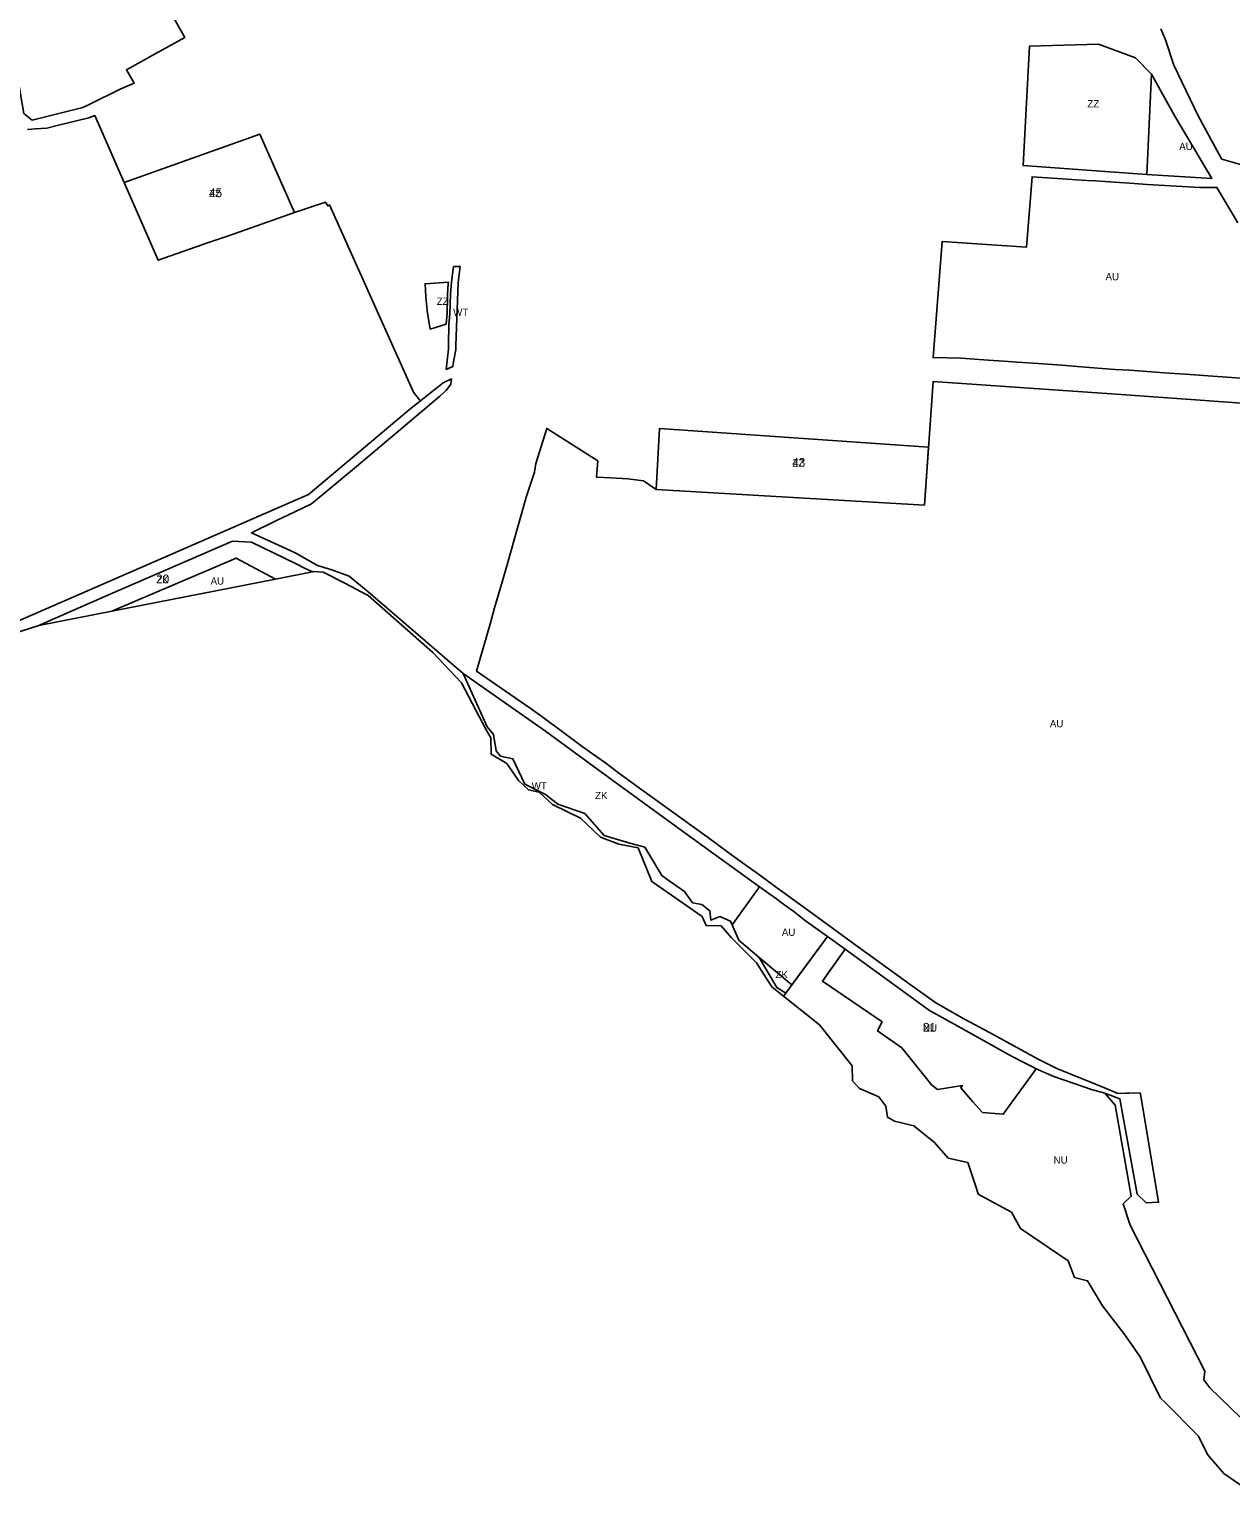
# Model space of a CAD drawing. Extents: x -541351 to -537540, y -1162694 to -1159725.
# Drawn here: x -540284 to -539459, y -1162132 to -1161126 of the extents above; entities that cross this region are included whole.
import ezdxf

# ---------------------------------------------------------------- set-up
doc = ezdxf.new("R2010")
doc.units = 0
for name, color, linetype in [('90640013', 7, 'Continuous'), ('90670013', 7, 'Continuous'), ('90670023', 7, 'Continuous'), ('90710013', 7, 'Continuous'), ('90710023', 7, 'Continuous'), ('90730013', 7, 'Continuous'), ('90730023', 7, 'Continuous'), ('90750013', 7, 'Continuous'), ('90910012', 7, 'Continuous'), ('ID_navrh', 7, 'Continuous')]:
    doc.layers.add(name, color=color, linetype=linetype)

msp = doc.modelspace()

# ---------------------------------------------------------------- linework, layer by layer
at = {"layer": '90640013'}
msp.add_lwpolyline([(-539992.48, -1161289.13), (-539987.89, -1161289.13), (-539989.14, -1161300.05), (-539990.78, -1161343.53), (-539990.84, -1161345.21), (-539990.88, -1161346.21), (-539992.72, -1161355.93), (-539992.93, -1161357.91), (-539992.93, -1161357.91), (-539997.43, -1161359.85), (-539997.43, -1161359.85), (-539995.85, -1161345.83), (-539995.82, -1161344), (-539995.8, -1161342.48), (-539995.6, -1161328.93), (-539994.93, -1161321.76), (-539994.48, -1161308.21), (-539993.82, -1161299.61)], close=True, dxfattribs=at)
msp.add_lwpolyline([(-540291.41, -1161532.59), (-540229.38, -1161505.57), (-540117.05, -1161456.65), (-540092, -1161445.78), (-540061.82, -1161420.37), (-540029.75, -1161393.37), (-540022.53, -1161387.29), (-539999.44, -1161369.08), (-539993.83, -1161366.31), (-539994.23, -1161370.06), (-539997.48, -1161374.21), (-540001.8, -1161378.25), (-540027.01, -1161399.42), (-540059.11, -1161426.38), (-540089.93, -1161452.04), (-540101.4, -1161457.57), (-540113.86, -1161463.58), (-540131.11, -1161472.1), (-540104.63, -1161484.12), (-540100.72, -1161485.89), (-540085.79, -1161494.36), (-540075.88, -1161497.34), (-540064.03, -1161501.76), (-540050.98, -1161512.57), (-539985.72, -1161568.53), (-539969.3, -1161605.18), (-539964.88, -1161610.52), (-539963.08, -1161621.82), (-539960.17, -1161625.29), (-539951.61, -1161627.12), (-539943.52, -1161644.57), (-539929.21, -1161651.77), (-539920.76, -1161658.22), (-539902.3, -1161664.83), (-539889.07, -1161679.88), (-539871.42, -1161685.18), (-539861.03, -1161687.93), (-539849.43, -1161707.39), (-539844.32, -1161711.05), (-539833.88, -1161718.35), (-539828.42, -1161726.07), (-539822.05, -1161727.27), (-539816.41, -1161731.54), (-539815.88, -1161737.88), (-539809.68, -1161735.52), (-539802.4, -1161738.55), (-539801.21, -1161741.26), (-539797.55, -1161749.61), (-539796.59, -1161751.79), (-539794.73, -1161753.35), (-539791.85, -1161755.78), (-539782.64, -1161763.55), (-539770.56, -1161784.1), (-539764.42, -1161788.07), (-539765.97, -1161790.189), (-539774.01, -1161783.8), (-539784.55, -1161767.2), (-539801.67, -1161750.2), (-539808.77, -1161741.8), (-539819.07, -1161741.58), (-539821.75, -1161735.54), (-539856.24, -1161711.42), (-539865.78, -1161688.26), (-539878.85, -1161685.75), (-539891.59, -1161680.9), (-539905.36, -1161667.95), (-539924.53, -1161658.61), (-539933.62, -1161650.11), (-539940.98, -1161648.48), (-539947.86, -1161642.02), (-539955.83, -1161630.36), (-539966.57, -1161624.08), (-539966.81, -1161612.76), (-539969.9, -1161607.26), (-539986.85, -1161575.11), (-540006.67, -1161554.17), (-540050.94, -1161515.14), (-540051.8, -1161514.68), (-540067.03, -1161506.49), (-540081.86, -1161499.15), (-540088.29, -1161498.6), (-540089.29, -1161498.8), (-540092.72, -1161497.13), (-540094.64, -1161496.2), (-540100.44, -1161493.38), (-540131.11, -1161478.47), (-540144.17, -1161477.68), (-540225.98, -1161513.32), (-540265.09, -1161530.36), (-540277.11, -1161535.69), (-540306.48, -1161545.1)], dxfattribs=at)
at = {"layer": '90670013'}
for points in [[(-539513.32, -1161157.12), (-539516.59, -1161225.93), (-539557.69, -1161223.11), (-539601.36, -1161219.9), (-539597.06, -1161137.85), (-539549.61, -1161136.48), (-539524.21, -1161145.9)], [(-539995.94, -1161299.88), (-539996.01, -1161301.19), (-539996.61, -1161308.12), (-539996.7, -1161321.56), (-539997.52, -1161328.72), (-540008.53, -1161332.12), (-540010.29, -1161321.38), (-540011.49, -1161309.94), (-540011.93, -1161301.03)]]:
    msp.add_lwpolyline(points, close=True, dxfattribs=at)
at = {"layer": '90670023'}
for points in [[(-540101.51, -1161252.18), (-540146.906, -1161268.009), (-540160.494, -1161272.74), (-540195.185, -1161284.798), (-540218.502, -1161231.526), (-540125.366, -1161198.286)], [(-539669.156, -1161452.992), (-539853.39, -1161442.31), (-539850.918, -1161400.307), (-539666.343, -1161413.186)]]:
    msp.add_lwpolyline(points, close=True, dxfattribs=at)
at = {"layer": '90710013'}
for points in [[(-539929.16, -1161608.15), (-539882.99, -1161642.02), (-539832.65, -1161678.79), (-539782.3, -1161715.02), (-539801.21, -1161741.26), (-539802.4, -1161738.55), (-539809.68, -1161735.52), (-539815.88, -1161737.88), (-539816.41, -1161731.54), (-539822.05, -1161727.27), (-539828.42, -1161726.07), (-539833.88, -1161718.35), (-539844.32, -1161711.05), (-539849.43, -1161707.39), (-539861.03, -1161687.93), (-539871.42, -1161685.18), (-539889.07, -1161679.88), (-539902.3, -1161664.83), (-539920.76, -1161658.22), (-539929.21, -1161651.77), (-539943.52, -1161644.57), (-539951.61, -1161627.12), (-539960.17, -1161625.29), (-539963.08, -1161621.82), (-539964.88, -1161610.52), (-539969.3, -1161605.18), (-539985.72, -1161568.53)], [(-539770.56, -1161784.1), (-539782.64, -1161763.55), (-539760.252, -1161782.438), (-539764.42, -1161788.07)]]:
    msp.add_lwpolyline(points, close=True, dxfattribs=at)
at = {"layer": '90710023'}
msp.add_lwpolyline([(-540094.64, -1161496.2), (-540094.64, -1161496.2), (-540092.72, -1161497.13), (-540089.29, -1161498.8), (-540089.29, -1161498.8), (-540114.639, -1161503.779), (-540141.7, -1161489.349), (-540226.878, -1161525.824), (-540277.11, -1161535.69), (-540265.09, -1161530.36), (-540225.98, -1161513.32), (-540144.17, -1161477.68), (-540131.11, -1161478.47), (-540100.44, -1161493.38)], close=True, dxfattribs=at)
at = {"layer": '90730013'}
msp.add_lwpolyline([(-539442.45, -1162132.43), (-539463.62, -1162117.77), (-539474.98, -1162104.91), (-539480.99, -1162092.24), (-539504.16, -1162068.99), (-539507.05, -1162066.09), (-539521.19, -1162037.78), (-539531.71, -1162022.73), (-539546.89, -1162002.65), (-539557.2, -1161985.49), (-539566.21, -1161983.21), (-539570.54, -1161971.78), (-539601.83, -1161950.6), (-539603.32, -1161949.59), (-539609.42, -1161938.46), (-539621.4, -1161931.95), (-539632.22, -1161926.07), (-539633.45, -1161922.3), (-539634.39, -1161919.41), (-539639.29, -1161904.36), (-539652.86, -1161901.34), (-539662.37, -1161890.73), (-539676.56, -1161879.19), (-539689.84, -1161876.05), (-539694.57, -1161873.26), (-539695.63, -1161865.58), (-539700.55, -1161859.23), (-539713.75, -1161853.49), (-539718.56, -1161848.39), (-539718.7, -1161838.04), (-539741.15, -1161809.91), (-539765.97, -1161790.189), (-539764.42, -1161788.07), (-539735.61, -1161749.14), (-539723.58, -1161757.8), (-539735.43, -1161774.65), (-539739.22, -1161779.81), (-539698.21, -1161807.88), (-539701.39, -1161814.06), (-539684.59, -1161825.63), (-539668.79, -1161845.45), (-539664.32, -1161850.94), (-539660.14, -1161854.23), (-539643.11, -1161851.4), (-539644.29, -1161853), (-539635.86, -1161862.6), (-539629.4, -1161869.96), (-539615.14, -1161871.21), (-539592.43, -1161840.03), (-539580.36, -1161845.31), (-539554.51, -1161854.21), (-539545.25, -1161856.85), (-539538.16, -1161865.08), (-539531.79, -1161901.38), (-539527.33, -1161927.46), (-539532.84, -1161932.62), (-539527.87, -1161947.38), (-539476.71, -1162047.7), (-539477.49, -1162053.65), (-539473.3, -1162058.96), (-539437.95, -1162093.1)], dxfattribs=at)
at = {"layer": '90730023'}
msp.add_lwpolyline([(-539603.34, -1161834.57), (-539594.06, -1161839.24), (-539592.43, -1161840.03), (-539615.14, -1161871.21), (-539629.4, -1161869.96), (-539635.86, -1161862.6), (-539644.29, -1161853), (-539643.11, -1161851.4), (-539660.14, -1161854.23), (-539664.32, -1161850.94), (-539668.79, -1161845.45), (-539684.59, -1161825.63), (-539701.39, -1161814.06), (-539698.21, -1161807.88), (-539739.22, -1161779.81), (-539735.43, -1161774.65), (-539723.58, -1161757.8), (-539665.66, -1161800.04), (-539644.29, -1161811.93), (-539622.87, -1161823.86), (-539611.45, -1161830.1)], close=True, dxfattribs=at)
at = {"layer": '90750013'}
for points in [[(-540185.73, -1161116.2), (-540176.86, -1161131.88), (-540197.26, -1161143.19), (-540216.93, -1161154.09), (-540211.6, -1161163.37), (-540221.12, -1161167.34), (-540242.426, -1161177.868), (-540246.8, -1161180.03), (-540281.58, -1161188.7), (-540287.3, -1161184.12), (-540288.43, -1161177.55), (-540294.74, -1161140.88), (-540298.48, -1161103.29)], [(-539452.22, -1161219.18), (-539464.98, -1161215.56), (-539466.8, -1161212.37), (-539481.41, -1161185.77), (-539498.11, -1161150.86), (-539503.79, -1161133.46), (-539506.91, -1161125.99)], [(-540284.83, -1161195.14), (-540279.25, -1161194.73), (-540271.57, -1161194.17), (-540264.39, -1161192.38), (-540242.79, -1161187.03), (-540238.6, -1161185.61), (-540218.502, -1161231.526), (-540195.185, -1161284.798), (-540160.494, -1161272.74), (-540146.906, -1161268.009), (-540101.51, -1161252.18), (-540080.23, -1161245.02), (-540078.75, -1161247.62), (-540077.53, -1161246.89), (-540019.81, -1161375.49), (-540015.659, -1161380.753), (-540015.115, -1161381.443), (-540022.53, -1161387.29), (-540029.75, -1161393.37), (-540061.82, -1161420.37), (-540092, -1161445.78), (-540117.05, -1161456.65), (-540229.38, -1161505.57), (-540291.41, -1161532.59)], [(-539442.69, -1161366.45), (-539490.23, -1161363.16), (-539504.725, -1161362.116), (-539528.28, -1161360.42), (-539538.26, -1161359.87), (-539547.15, -1161359.17), (-539561.62, -1161358.04), (-539574.79, -1161357.02), (-539591.1, -1161355.75), (-539605.28, -1161354.9), (-539614.66, -1161354.26), (-539625.23, -1161353.54), (-539644.31, -1161352.21), (-539663.28, -1161351.67), (-539657.046, -1161272.103), (-539599.126, -1161275.987), (-539595.35, -1161227.56), (-539581.18, -1161228.48), (-539564.86, -1161229.58), (-539557.83, -1161230.05), (-539551.82, -1161230.45), (-539535.3, -1161231.55), (-539528.25, -1161232.02), (-539516.42, -1161232.77), (-539480.24, -1161235.04), (-539468.39, -1161234.85), (-539453.999, -1161259.118)], [(-539437.95, -1162093.1), (-539473.3, -1162058.96), (-539477.49, -1162053.65), (-539476.71, -1162047.7), (-539527.87, -1161947.38), (-539532.84, -1161932.62), (-539532.84, -1161932.62), (-539527.33, -1161927.46), (-539531.79, -1161901.38), (-539538.16, -1161865.08), (-539545.25, -1161856.85), (-539535.16, -1161860.62), (-539523.09, -1161926.07), (-539517.03, -1161931.97), (-539508.43, -1161931.66), (-539520.5, -1161859.91), (-539521.049, -1161856.579), (-539528.75, -1161856.77), (-539530.99, -1161856.83), (-539536.48, -1161856.9), (-539536.48, -1161856.9), (-539545.54, -1161853.03), (-539556.8, -1161848.47), (-539562.42, -1161846.2), (-539578.2, -1161839.8), (-539591.16, -1161833.38), (-539621.96, -1161816.51), (-539634.29, -1161809.82), (-539641.65, -1161805.83), (-539661.42, -1161794.73), (-539678.99, -1161782.08), (-539719.52, -1161752.83), (-539747.55, -1161732.32), (-539770.78, -1161715.47), (-539783.08, -1161706.4), (-539792.51, -1161699.77), (-539803.22, -1161692.04), (-539811.18, -1161685.91), (-539818.4, -1161680.77), (-539828.73, -1161673.29), (-539867.18, -1161645.5), (-539879.18, -1161636.73), (-539888.88, -1161629.56), (-539896.23, -1161624.24), (-539904.11, -1161618.82), (-539923.06, -1161604.56), (-539925.41, -1161603.03), (-539931.76, -1161598.16), (-539939.69, -1161592.41), (-539976.59, -1161567.1), (-539967.01, -1161533.79), (-539964.28, -1161523.63), (-539961.04, -1161512.78), (-539957.73, -1161500.99), (-539955, -1161491.4), (-539948.74, -1161469.44), (-539942.28, -1161446.78), (-539936.89, -1161430.47), (-539935.81, -1161424.54), (-539928.46, -1161400.38), (-539893.29, -1161422.66), (-539894.17, -1161433.83), (-539884.33, -1161434.31), (-539872.87, -1161434.88), (-539861.95, -1161436.3), (-539853.39, -1161442.31), (-539669.156, -1161452.992), (-539663.153, -1161368.023), (-539603.775, -1161372.215), (-539534.132, -1161377.143), (-539505.512, -1161379.19), (-539381.181, -1161387.997)]]:
    msp.add_lwpolyline(points, dxfattribs=at)
for points in [[(-539516.59, -1161225.93), (-539513.32, -1161157.12), (-539497.36, -1161186), (-539472.01, -1161228.75)], [(-540114.639, -1161503.779), (-540114.639, -1161503.779), (-540226.878, -1161525.824), (-540141.7, -1161489.349)], [(-539735.61, -1161749.14), (-539760.252, -1161782.438), (-539782.64, -1161763.55), (-539791.85, -1161755.78), (-539794.73, -1161753.35), (-539796.59, -1161751.79), (-539797.55, -1161749.61), (-539801.21, -1161741.26), (-539782.3, -1161715.02), (-539775.92, -1161719.61), (-539772.29, -1161722.22), (-539770.71, -1161723.36), (-539769.25, -1161724.43), (-539762.51, -1161729.49), (-539758.86, -1161732.11), (-539755.49, -1161734.76), (-539751.72, -1161737.63)]]:
    msp.add_lwpolyline(points, close=True, dxfattribs=at)
at = {"layer": '90910012'}
msp.add_lwpolyline([(-539723.58, -1161757.8), (-539739.22, -1161779.81), (-539698.21, -1161807.88), (-539701.39, -1161814.06), (-539684.59, -1161825.63), (-539668.79, -1161845.45), (-539664.32, -1161850.94), (-539660.14, -1161854.23), (-539643.11, -1161851.4), (-539644.29, -1161853), (-539635.86, -1161862.6), (-539629.4, -1161869.96), (-539615.14, -1161871.21), (-539592.43, -1161840.03)], dxfattribs=at)

# ---------------------------------------------------------------- texts
at = {"layer": '90640013'}
for rotation, p in [(0, (-539992.66, -1161323.075)), (360, (-539938.746, -1161648.23))]:
    msp.add_text('WT', height=5, rotation=rotation, dxfattribs=at).set_placement(p)
at = {"layer": '90670013'}
for rotation, p in [(0, (-539557.34, -1161179.919)), (360, (-540003.935, -1161315.578))]:
    msp.add_text('ZZ', height=5, rotation=rotation, dxfattribs=at).set_placement(p)
at = {"layer": '90670023'}
for rotation, p in [(0, (-540160.168, -1161241.542)), (360, (-539759.881, -1161426.649))]:
    msp.add_text('ZZ', height=5, rotation=rotation, dxfattribs=at).set_placement(p)
at = {"layer": '90710013'}
for p in [(-539895.24, -1161654.895), (-539771.446, -1161777.793)]:
    msp.add_text('ZK', height=5, rotation=360, dxfattribs=at).set_placement(p)
at = {"layer": '90710023'}
msp.add_text('ZK', height=5, rotation=0, dxfattribs=at).set_placement((-540196.467, -1161506.685))
at = {"layer": '90730013'}
msp.add_text('NU', height=5, rotation=0, dxfattribs=at).set_placement((-539580.545, -1161905.118))
at = {"layer": '90730023'}
msp.add_text('NU', height=5, rotation=0, dxfattribs=at).set_placement((-539670.205, -1161814.505))
at = {"layer": '90750013'}
for rotation, p in [(360, (-539494.3, -1161209.25)), (0, (-539544.913, -1161298.63)), (360, (-540159.157, -1161507.586)), (0, (-539583.109, -1161605.523)), (0, (-539767.061, -1161748.729))]:
    msp.add_text('AU', height=5, rotation=rotation, dxfattribs=at).set_placement(p)
at = {"layer": 'ID_navrh'}
for s, p in [('45', (-540160.168, -1161241.542)), ('43', (-539759.881, -1161426.649)), ('20', (-540196.467, -1161506.685)), ('21', (-539670.205, -1161814.505))]:
    msp.add_text(s, height=6, rotation=0, dxfattribs=at).set_placement(p)

doc.saveas('drawing.dxf')
